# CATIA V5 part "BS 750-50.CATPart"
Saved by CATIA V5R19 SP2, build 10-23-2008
Part number: BS 750-50
Bounding box of the stored display mesh (mm): x -22.494 to 22.494, y -22.494 to 22.494, z 0 to 132
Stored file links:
  C:\Users\Bora\Desktop\3D Katı model\BS serisi\BS 750\BS 750-50.CATPart
  C:\Program Files\Dassault Systemes\B19\intel_a\reffiles\standard\MetricThickPitch.txt
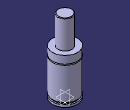
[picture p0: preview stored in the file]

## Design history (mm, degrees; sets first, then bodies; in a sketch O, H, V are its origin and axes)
Body1 (main body)
  Sketch1 on yz-plane, origin (0, 0, 0), H (0, 1, 0), V (0, 0, 1)
    point P3 (12.5, 131)
    point P5 (12.5, 131)
    point P7 (22.5, 67.5)
    point P8 (22.5, 65.5)
    point P12 (22.5, 65.5)
    point P13 (22.5, 67.5)
    line L1 (22.5, 0) -> (22.5, 4)
    line L2 (12.5, 131) -> (12.5, 81)
    arc A1 centre (11.5, 131) radius 1 from (12.5, 131) to (11.5, 132) ccw
    arc A2 centre (22.5, 66.5) radius 1 from (22.5, 67.5) to (22.5, 65.5) ccw
    line L3 (20, 7.5) -> (20, 4)
    line L4 (22.5, 7.5) -> (22.5, 65.5)
    line L5 (22.5, 67.5) -> (22.5, 81)
    line L6 (11.5, 132) -> (0, 132)
    point P15 (0, 132)
    line L7 (12.5, 81) -> (22.5, 81)
    line L8 (0, 0) -> (22.5, 0)
    line L9 (20, 7.5) -> (22.5, 7.5)
    line L10 (20, 4) -> (22.5, 4)
    coincidence: P15 V, P3 P5, P7 P13, P8 P12
    tangency: L6 A1
    horizontal: L7 H, L8 H, L9 H, L10 H
  Shaft1: profile Sketch1, axis Sketch1.V, angle 360
  Sketch2 on face of Shaft1 from Sketch1.L8, origin (0, 0, 0), H (1, 0, 0), V (0, -1, 0)
    point P1 (10, 0)
    distance P1 V = 10
  Hole1: placed by Sketch2, at (10, 0, 0) direction (0, 0, 1), diameter 6.647, depth 4, threaded "M8", thread diameter 8, thread depth 4, pitch 1.25
  CircPattern1: of Hole1, instances 2, angular step 180, axis from xy-plane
